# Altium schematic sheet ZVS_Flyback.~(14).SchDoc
size 431 x 279 mm; Date: Not shown in title block; ApprovedBy: Not shown in title block; CheckedBy: Not shown in title block; Author: Not shown in title block; CompanyName: Not shown in title block; Engineer: Not shown in title block; Organization: Not shown in title block; Address1: Not shown in title block; Address2: Not shown in title block; Address3: Not shown in title block; Address4: Not shown in title block; DocumentNumber: 2; Revision: Use project parameter SCH_Rev; SheetNumber: 2; SheetTotal: 2; PageSetup: Record=PageOptions¦CenterHorizontal=True¦CenterVertical=True¦PrintScale=1.00¦XCorrection=1.00¦YCorrection=1.00¦PrintKind=0¦BorderSize=5000000¦LeftOffset=0¦BottomOffset=0¦Orientation=2¦PaperLength=1000¦PaperWidth=1000¦Scale=100¦PaperSource=15¦PrintQuality=600¦MediaType=1¦DitherType=10¦PaperKind=Letter¦PrintScaleMode=1
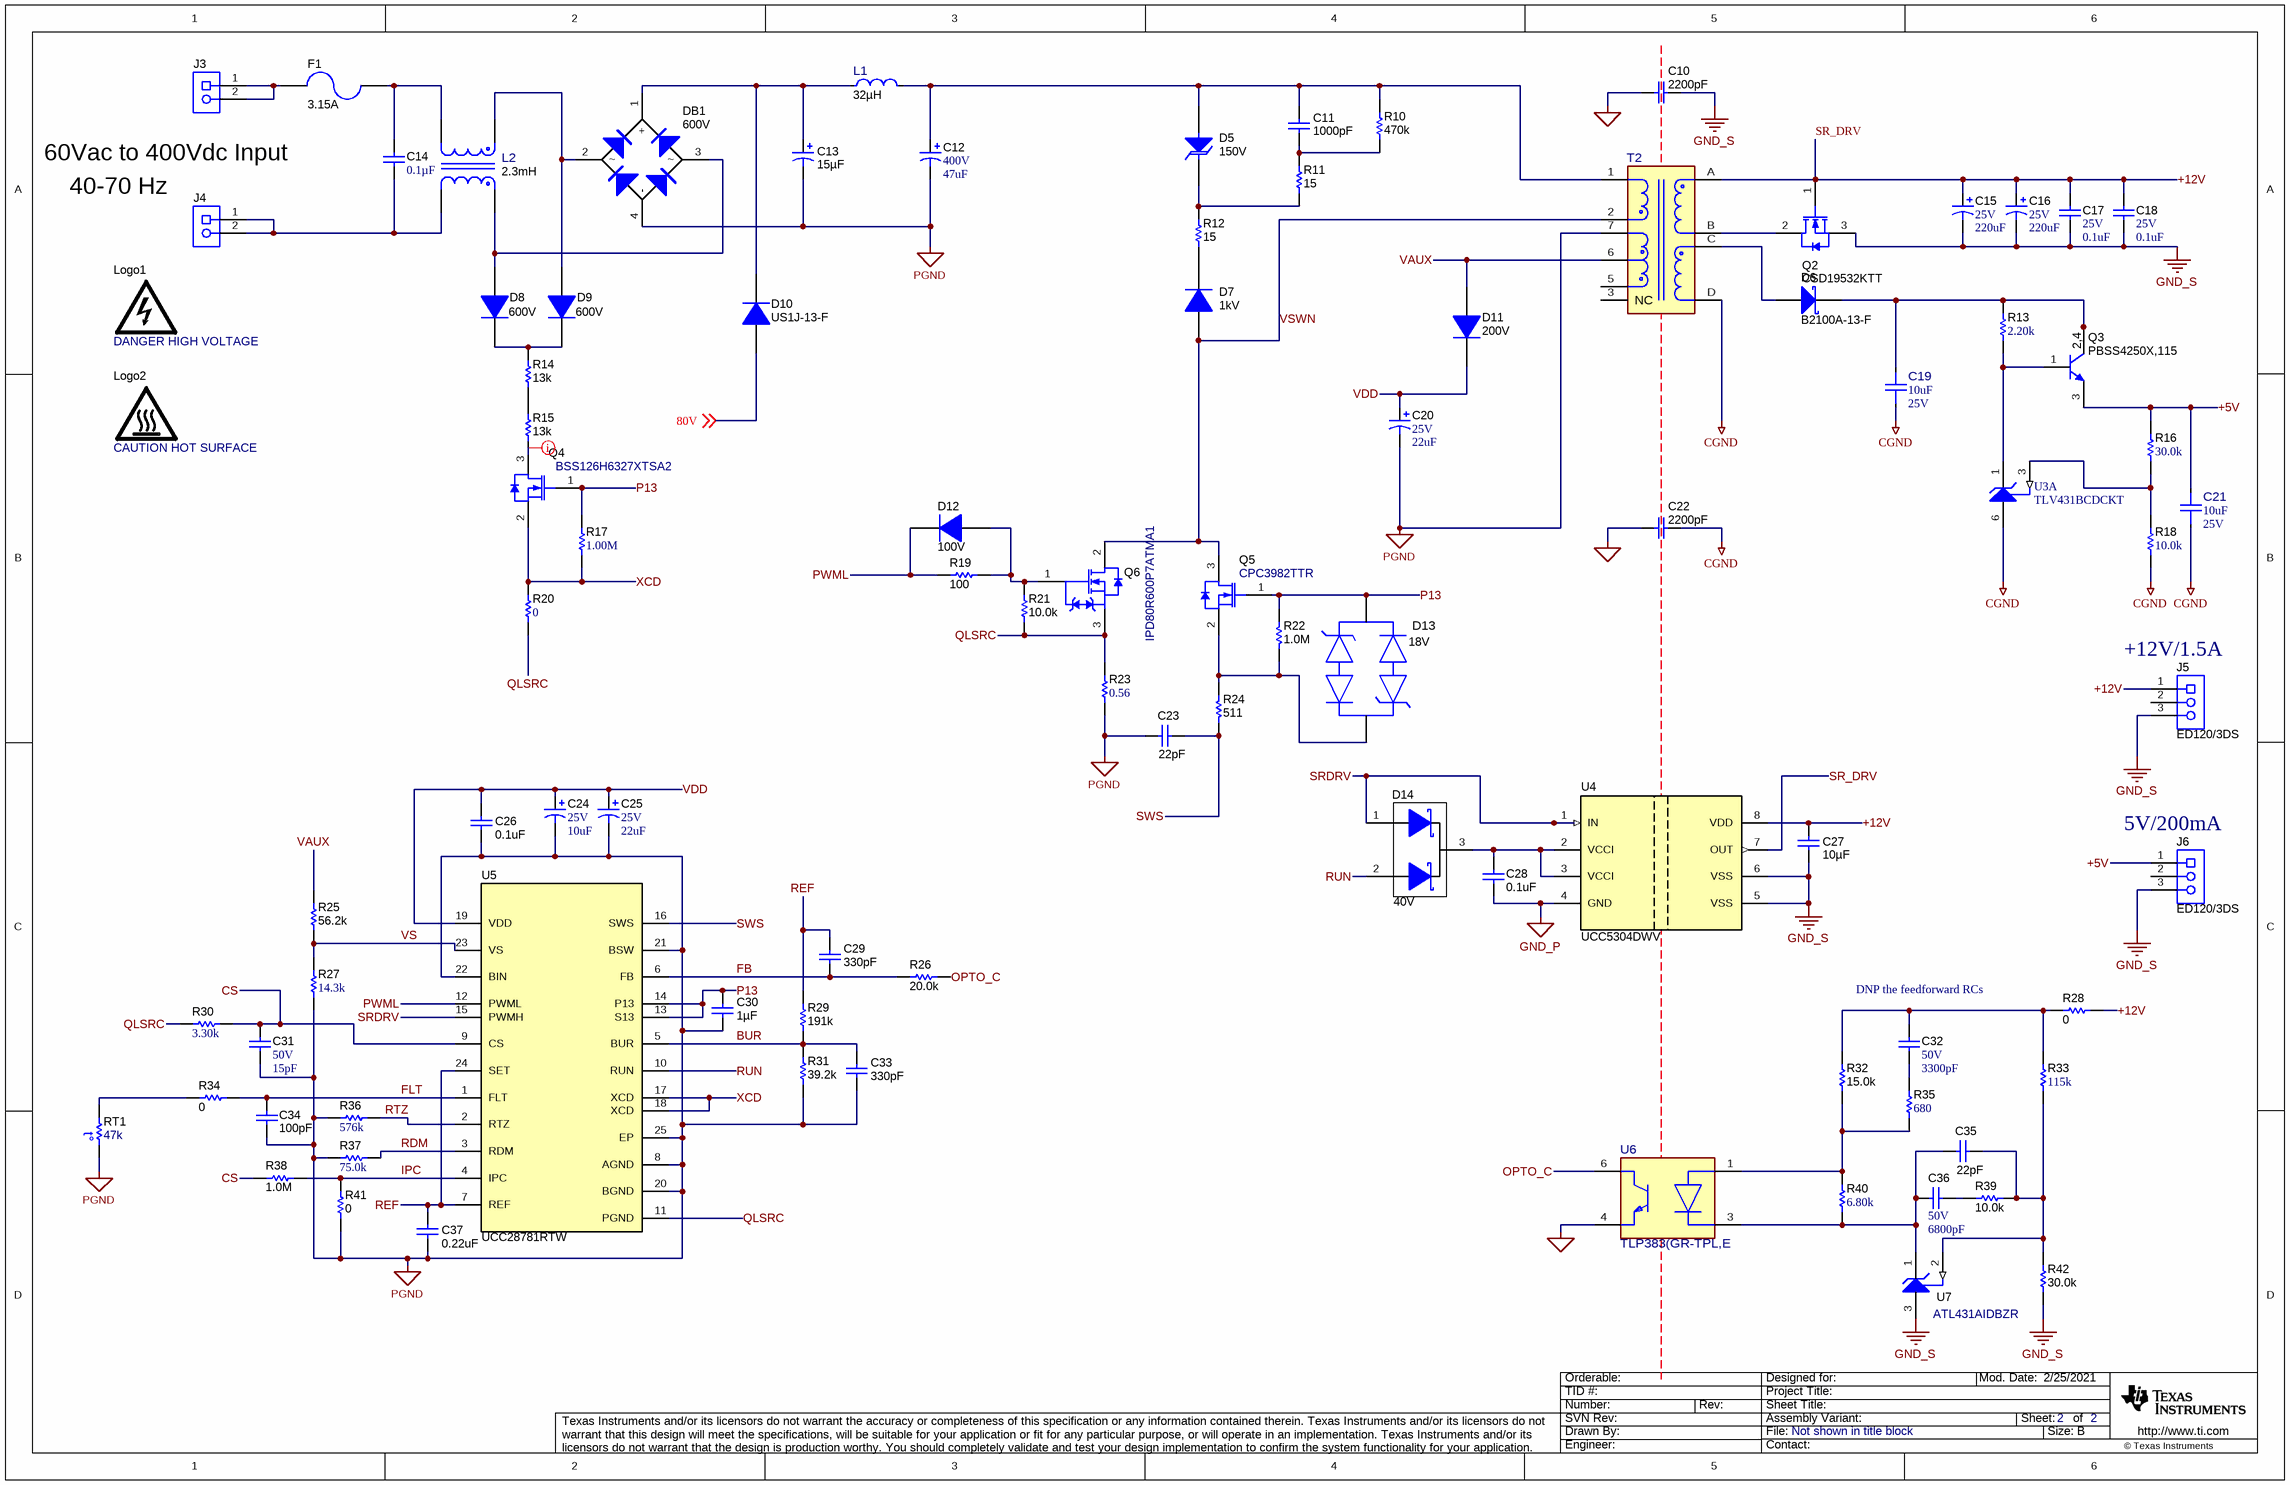
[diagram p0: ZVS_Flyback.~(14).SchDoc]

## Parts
C10  ValueDisplayed: 2200pF  [C900_9x13]  (hidden comment: C921U222MVVDBA7317)
C11  ValueDisplayed: 1000pF  [1206L]  (hidden comment: GRM31BR72J102KW01L)
C12  VDC_V: 400V  ValueDisplayed: 47uF  [CAPPR7.5-16x25]  (hidden comment: UCS2G470MHD)
C13  ValueDisplayed: 15µF  [UVC_1000x1600]  (hidden comment: UVC2G150MPD)
C14  ValueDisplayed: 0.1µF  [B32933_600x1500x2650]  (hidden comment: B32933A3104K000)
C15  VDC_V: 25V  ValueDisplayed: 220uF  [BT_1000x1250]  (hidden comment: UBT1E221MPD1TD)
C16  VDC_V: 25V  ValueDisplayed: 220uF  [BT_1000x1250]  (hidden comment: UBT1E221MPD1TD)
C17  VDC_V: 25V  ValueDisplayed: 0.1uF  [0603]  (hidden comment: 06033D104KAT2A)
C18  VDC_V: 25V  ValueDisplayed: 0.1uF  [0603]  (hidden comment: 06033D104KAT2A)
C19  ValueDisplayed: 10uF  VDC_V: 25V  [FP-ZRB18AR61E106ME01L_0603-MFG]  (hidden comment: ZRB18AR61E106ME01L)
C20  VDC_V: 25V  ValueDisplayed: 22uF  [SM_RADIAL_D]  (hidden comment: EEE-FC1E220P)
C21  ValueDisplayed: 10uF  VDC_V: 25V  [FP-ZRB18AR61E106ME01L_0603-MFG]  (hidden comment: ZRB18AR61E106ME01L)
C22  ValueDisplayed: 2200pF  [C900_9x13]  (hidden comment: C921U222MVVDBA7317)
C23  ValueDisplayed: 22pF  [0402S]  (hidden comment: GCM1555C1H220JA16D)
C24  VDC_V: 25V  ValueDisplayed: 10uF  [CAPSMT_62_D55]  (hidden comment: EMVA250ADA100MD55G)
C25  VDC_V: 25V  ValueDisplayed: 22uF  [SM_RADIAL_D]  (hidden comment: EEE-FC1E220P)
C26  ValueDisplayed: 0.1uF  [0402S]  (hidden comment: GRM155R71H104ME14D)
C27  ValueDisplayed: 10µF  [1206_180L]  (hidden comment: C1206C106J3RACAUTO)
C28  ValueDisplayed: 0.1uF  [0402S]  (hidden comment: GRM155R71H104ME14D)
C29  ValueDisplayed: 330pF  [0402S]  (hidden comment: GRM155R71H331KA01D)
C30  Cap_F: 1µF  [0603S]  (hidden comment: CGA3E1X7R1V105K080AC)
C31  VDC_V: 50V  ValueDisplayed: 15pF  [0402]  (hidden comment: CC0402JRNPO9BN150)
C32  VDC_V: 50V  ValueDisplayed: 3300pF  [0402]  (hidden comment: GRM155R71H332KA01D)
C33  ValueDisplayed: 330pF  [0402S]  (hidden comment: GRM155R71H331KA01D)
C34  ValueDisplayed: 100pF  [0402S]  (hidden comment: GRM1555C1H101JA01D)
C35  ValueDisplayed: 22pF  [0402S]  (hidden comment: GCM1555C1H220JA16D)
C36  VDC_V: 50V  ValueDisplayed: 6800pF  [0402]  (hidden comment: GRM155R71H682KA88D)
C37  ValueDisplayed: 0.22uF  [0402S]  (hidden comment: GRM155R71C224KA12D)
D5  VRWM: 150V  [SMA]  (hidden comment: SMAJ150A)
D6  B2100A-13-F  [SMA]
D7  Vr_V: 1kV  [SMA]  (hidden comment: MRA4007T3G)
D8  Vr_V: 600V  [TUMD2SM]  (hidden comment: RFU02VSM6STR)
D9  Vr_V: 600V  [TUMD2SM]  (hidden comment: RFU02VSM6STR)
D10  US1J-13-F  [SMA]
D11  Vr_V: 200V  [SOD-123H]  (hidden comment: CSFMT104-HF)
D12  Vr_V: 100V  [SOD-323]  (hidden comment: BAS316,115)
D13  CDSOD323-T18C  [FP-CDSOD323-T18C_SOD323-MFG]  (value not drawn)
D14  Vr_V: 40V  [SOT-323]  (hidden comment: BAS40W-05-7-F)
DB1  value 600V  [Z4-D]  (hidden comment: Z4DGP406L-HF)
F1  Irating_A: 3.15A  [FUSE_392]  (hidden comment: 39213150000)
J3  ED120/2DS  [On-Shore_ED120_2DS]  (value not drawn)
J4  ED120/2DS  [On-Shore_ED120_2DS]  (value not drawn)
J5  ED120/3DS  [On-Shore_ED120_3DS]
J6  ED120/3DS  [On-Shore_ED120_3DS]
L1  Ind_H: 32µH  [FP-7447052_PTH_D10MM0-MFG]  (hidden comment: 7447052)
L2  Ind_H: 2.3mH  [FP-RLTI-1387_PTH_CMC_0IN38_0IN60-MFG]  (hidden comment: RLTI-1387)
Logo1  DANGER HIGH VOLTAGE  [IEC_HighVoltage_Small]  (no BOM)
Logo2  CAUTION HOT SURFACE  [IEC_HotSurface_Small]  (no BOM)
Q2  CSD19532KTT  [KTT0002A]
Q3  PBSS4250X,115  [SOT-89-3]
Q4  BSS126H6327XTSA2  [SOT-23L]
Q5  CPC3982TTR  [SOT-23L]
Q6  IPD80R600P7ATMA1  [DPAK]
R10  ValueDisplayed: 470k  [0805_HV1]  (hidden comment: CRCW0805470KJNEA)
R11  ValueDisplayed: 15  [0805_HV1]  (hidden comment: CRCW080515R0JNEA)
R12  ValueDisplayed: 15  [0805_HV1]  (hidden comment: CRCW080515R0JNEA)
R13  ValueDisplayed: 2.20k  [0603]  (hidden comment: RC0603FR-072K2L)
R14  ValueDisplayed: 13k  [1206L]  (hidden comment: CRCW120613K0JNEA)
R15  ValueDisplayed: 13k  [1206L]  (hidden comment: CRCW120613K0JNEA)
R16  ValueDisplayed: 30.0k  [0603]  (hidden comment: RC0603FR-0730KL)
R17  ValueDisplayed: 1.00M  [0603]  (hidden comment: MCT06030C1004FP500)
R18  ValueDisplayed: 10.0k  [0402]  (hidden comment: ERJ-2RKF1002X)
R19  ValueDisplayed: 100  [0805_HV1]  (hidden comment: CRCW0805100RJNEA)
R20  ValueDisplayed: 0  [0603]  (hidden comment: RC0603JR-070RL)
R21  ValueDisplayed: 10.0k  [0402S]  (hidden comment: CRCW040210K0FKED)
R22  ValueDisplayed: 1.0M  [0402S]  (hidden comment: CRCW04021M00JNED)
R23  ValueDisplayed: 0.56  [1206]  (hidden comment: ERJ-8RQFR56V)
R24  ValueDisplayed: 511  [0402S]  (hidden comment: CRCW0402511RFKED)
R25  ValueDisplayed: 56.2k  [0402S]  (hidden comment: CRCW040256K2FKED)
R26  ValueDisplayed: 20.0k  [0402S]  (hidden comment: CRCW040220K0FKED)
R27  ValueDisplayed: 14.3k  [0402]  (hidden comment: CRCW040214K3FKED)
R28  ValueDisplayed: 0  [0402S]  (hidden comment: RC0402JR-070RL)
R29  ValueDisplayed: 191k  [0402S]  (hidden comment: CRCW0402191KFKED)
R30  ValueDisplayed: 3.30k  [0402]  (hidden comment: RK73H1ETTP3301F)
R31  ValueDisplayed: 39.2k  [0402S]  (hidden comment: CRCW040239K2FKED)
R32  ValueDisplayed: 15.0k  [0402S]  (hidden comment: CRCW040215K0FKED)
R33  ValueDisplayed: 115k  [0402]  (hidden comment: RC1005F1153CS)
R34  ValueDisplayed: 0  [0402S]  (hidden comment: CRCW04020000Z0EDHP)
R35  ValueDisplayed: 680  [0603]  (hidden comment: RC0603FR-07680RL)
R36  ValueDisplayed: 576k  [0402]  (hidden comment: CRCW0402576KFKED)
R37  ValueDisplayed: 75.0k  [0402]  (hidden comment: CRCW040275K0FKED)
R38  ValueDisplayed: 1.0M  [0402S]  (hidden comment: CRCW04021M00JNED)
R39  ValueDisplayed: 10.0k  [0402S]  (hidden comment: CRCW040210K0FKED)
R40  ValueDisplayed: 6.80k  [0603]  (hidden comment: RC0603FR-076K8L)
R41  ValueDisplayed: 0  [0402S]  (hidden comment: CRCW04020000Z0EDHP)
R42  ValueDisplayed: 30.0k  [0402S]  (hidden comment: CRCW040230K0FKED)
RT1  value 47k  [0603S]  (hidden comment: NCP18WB473J03RB)
T2  RLTI-1324  [FP-RLTI-1324_PTH_0IN980_0IN766-MFG]  (value not drawn)
U3  TLV431BCDCKT  [DCK0006A_N]  (part A of 2)
U4  UCC5304DWV  [DWV0008A]
U5  UCC28781RTW  [RTW0024B]
U6  TLP383(GR-TPL,E  [FP-TLP383(GR-TPL,E_SO6-4-MFG]
U7  ATL431AIDBZR  [DBZ0003A_L]

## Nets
CGND: C19.1 C21.1 C22.1 R18.1 T2.D U3.6(ANODE)
GND2: C10.2 C22.2 U6.4(Emitter)
GND_P: C28.2 U4.4(GND)
GND_S: C10.1 C15.2(-) C16.2(-) C17.2 C18.2 C27.2 J5.3 J6.3 Q2.3(S) R42.2 U4.5(VSS) U4.6(VSS) U7.3(ANODE)
PGND: C12.2(-) C13.2(-) C20.2(-) C23.1 C24.2(-) C25.2(-) C26.2 C30.2 C31.2 C33.2 C34.1 C37.2 DB1.4(-) R23.1 R27.1 R31.2 R36.1 R37.1 R41.1 RT1.2 T2.7 U5.8(AGND) U5.20(BGND) U5.21(BSW) U5.22(BIN) U5.25(EP)
80V: D10.2(A) ; off-sheet 80V
+5V: C21.2 J6.1 Q3.3(E) R16.2
+12V: C15.1(+) C16.1(+) C17.1 C18.1 C27.1 J5.1 Q2.1(G) R28.1 T2.A U4.7(OUT) U4.8(VDD)  [also labelled SR_DRV]
BUR: C33.1 R29.2 R31.1 U5.5(BUR)
CS: C31.1 R30.2 R38.2 U5.9(CS)
FB: C29.2 R26.1 U5.6(FB)
FLT: C34.2 R34.2 U5.1(FLT)
IPC: R38.1 R41.2 U5.4(IPC)
OPTO_C: R26.2 U6.6(Collector)
P13: C30.1 D13.2 Q4.1(G) Q5.1(G) R17.2 R22.2 U5.13(S13) U5.14(P13)
PWML: D12.1(K) R19.1 U5.12(PWML)
QLSRC: Q6.3(S) R20.1 R21.1 R23.2 R30.1 U5.11(PGND)
RDM: R37.2 U5.3(RDM)
REF: C29.1 C37.1 R29.1 U5.7(REF) U5.24(SET)
RTZ: R36.2 U5.2(RTZ)
RUN: D14.2(A) U5.10(RUN)
SRDRV: D14.1(A) U4.1(IN) U5.15(PWMH)
SWS: C23.2 R24.1 U5.16(SWS)
VAUX: D11.2(A) R25.1 T2.6
VDD: C20.1(+) C24.1(+) C25.1(+) C26.1 D11.1(K) U5.19(VDD)
VS: R25.2 R27.2 U5.23(VS)
VSWN: D7.2(A) Q5.3(D) Q6.2(D) T2.2
XCD: Q4.2(S) R17.1 R20.2 U5.17(XCD) U5.18(XCD)
NetC11_1: C11.1 C12.1(+) D5.2(A) L1.2 R10.2 T2.1
NetC11_2: C11.2 R10.1 R11.2
NetC13_1: C13.1(+) D10.1(K) DB1.1(+) L1.1
NetC14_1: C14.1 F1.1 L2.3
NetC14_2: C14.2 J4.1 J4.2 L2.2
NetC19_2: C19.2 D6.1(K) Q3.2(C) Q3.4(C) R13.2
NetC28_1: C28.1 D14.3(K) U4.2(VCCI) U4.3(VCCI)
NetC32_1: C32.1 R28.2 R32.2 R33.2
NetC32_2: C32.2 R35.2
NetC35_1: C35.1 C36.2 R40.1 U6.3(Cathode) U7.1(CATHODE)
NetC35_2: C35.2 R33.1 R39.2 R42.1 U7.2(REF)
NetC36_1: C36.1 R39.1
NetD5_1: D5.1(K) R11.1 R12.2
NetD6_2: D6.2(A) T2.C
NetD7_1: D7.1(K) R12.1
NetD8_1: D8.1(K) D9.1(K) R14.1
NetD8_2: D8.2(A) DB1.3 L2.1
NetD9_2: D9.2(A) DB1.2 L2.4
NetD12_2: D12.2(A) Q6.1(G) R19.2 R21.2
NetD13_1: D13.1 Q5.2(S) R22.1 R24.2
NetF1_2: F1.2 J3.1 J3.2
NetQ2_2: Q2.2(D) T2.B
NetQ3_1: Q3.1(B) R13.1 U3.1(CATHODE)
NetQ4_3: Q4.3(D) R15.2
NetR14_2: R14.2 R15.1
NetR16_1: R16.1 R18.2 U3.3(REF)
NetR32_1: R32.1 R35.1 R40.2 U6.1(Anode)
NetR34_1: R34.1 RT1.1

Not connected (* = marked no-connect by the designer): J5 2; J6 2; T2 3(NC) 5

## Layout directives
net class HV: NetQ4_3

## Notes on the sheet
- 60Vac to 400Vdc Input
- 40-70 Hz
- (near D13) 18V
- (near J5) +12V/1.5A
- (near J6) 5V/200mA
- (near C32) DNP the feedforward RCs

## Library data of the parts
C10 C22 = CMP-0078358-1: CAP, CERM, 2200 pF, X1 400 VAC/Y1 400 VAC, +/- 20%, Y5V, D9xL13mm; Manufacturer: Kemet; Cap_F: 2.2nF; SizeAreaWB_mm2: 121; VAC_X: 400V; SizeArea_mm2: 81; AEC Qualified: N; AEC Category: Q200; Value: 2200pF; TaMax_C: 125°C; SizeZ_mm: 13; TaMin_C: -40°C; SizeY_mm: 9; U/M: EA; AC_Safety: X1Y1; Cap_Case: 9x13mm
C11 = CMP-0008909-2: CAP, CERM, 1000 pF, 630 V, +/- 10%, X7R, 1206; Manufacturer: MuRata; TaMin_C: -55°C; Polarized: N; SizeAreaWB_mm2: 10.92; Value1: Unknown; U/M: EA; Value: 1000pF; TaMax_C: 125°C; SizeZ_mm: 1.35; SizeX_mm: 3.2; SizeY_mm: 1.6; Cap_Case: 1206; Value2: 630V; SizeArea_mm2: 5.12; Cap_F: 1nF; AEC Category: Q200
C12 = CMP-0010241-2: CAP, AL, 47 uF, 400 V, +/- 20%, TH; Manufacturer: Nichicon; TaMin_C: -40°C; Polarized: Y; SizeAreaWB_mm2: 324; Value1: Unknown; U/M: EA; Value: 47uF; TaMax_C: 105°C; SizeZ_mm: 25; SizeX_mm: 16; Cap_Case: Radial  16x25mm; SizeArea_mm2: 256; CompType: Capacitor; AEC Qualified: N; Cap_F: 47µF; IRMS_A: 1.18A; AEC Category: Q200
C13 = CMP-0860955-2: CAP, AL, 15 µF, 400 V, +/- 20%, AEC-Q200 Grade 2, TH; Manufacturer: Nichicon; SizeArea_mm2: 100; CompType: Capacitor; Value2: 400V; SizeZ_mm: 18; IRMS_A: 180mA; Polarized: Y; SizeX_mm: 10; Value: 15uF; TaMin_C: -40°C; AEC Grade: 2; U/M: EA; SizeAreaWB_mm2: 144; Cap_Case: 10x16; TaMax_C: 105°C; AEC Category: Q200
C14 = CMP-0077664-2: CAP, Film, 0.1 µF, X2 305 VAC, +/- 10%, AEC-Q200 Grade 2, TH; Manufacturer: TDK; TaMin_C: -40°C; Polarized: N; SizeAreaWB_mm2: 210.0; Value: 0.1uF; TaMax_C: 105°C; VAC_X: 305; SizeZ_mm: 15.0; SizeX_mm: 26.0; SizeY_mm: 5.5; SizeArea_mm2: 143.0; AEC Qualified: Y; Cap_F: 100nF; AEC Grade: 2; AEC Category: Q200
C15 C16 = CMP-0010527-1: CAP, AL, 220 uF, 25 V, +/- 20%, 0.1 ohm, TH; Manufacturer: Nichicon; TaMin_C: -40°C; ESR_ohm: 1d; Polarized: Y; SizeAreaWB_mm2: 144; Value1: 0.1 ohm; U/M: EA; Value: 220uF; TaMax_C: 125°C; SizeZ_mm: 14.5; SizeX_mm: 10; Cap_Case: 10x12.5mm; SizeArea_mm2: 100; CompType: Capacitor; Cap_F: 220µF; IRMS_A: 6.8dA; AEC Category: Q200
C17 C18 = CMP-0006758-5: CAP, CERM, 0.1 uF, 25 V, +/- 10%, X5R, 0603; Manufacturer: AVX; TaMin_C: -55°C; ESR_ohm: 0.048; Polarized: N; SizeAreaWB_mm2: 4.68; Value1: 0.048 ohm; U/M: EA; Value: 0.1uF; TaMax_C: 85°C; SizeZ_mm: 1; SizeX_mm: 1.6; SizeY_mm: 0.8; SizeArea_mm2: 1.28; Cap_F: 100nF; IRMS_A: 5.3dA; AEC Category: Q200
C19 C21 = CMP-0094458-1: 10µF ±20% 25V Ceramic Capacitor X5R 0603 (1608 Metric); Manufacturer: Murata Electronics; SizeZ_mm: 1.2mm; AEC Qualified: No
C20 C25 = CMP-0010654-1: CAP, AL, 22 uF, 25 V, +/- 20%, 1 ohm, SMD; Manufacturer: Panasonic; TaMin_C: -40°C; ESR_ohm: 1; Polarized: Y; SizeAreaWB_mm2: 84.28; Value1: 1 ohm; U/M: EA; Value: 22uF; TaMax_C: 105°C; SizeZ_mm: 5.4; SizeX_mm: 7.8; SizeY_mm: 6.6; Cap_Case: D; SizeArea_mm2: 51.48; CompType: Capacitor; Cap_F: 22µF; IRMS_A: 1.15dA; AEC Category: Q200
C23 C35 = CMP-0006348-2: CAP, CERM, 22 pF, 50 V, +/- 5%, C0G/NP0, AEC-Q200 Grade 1, 0402; Manufacturer: MuRata; TaMin_C: -55°C; Polarized: N; SizeAreaWB_mm2: 3; Value1: Unknown; U/M: EA; Value: 22pF; TaMax_C: 125°C; SizeZ_mm: 0.6; SizeX_mm: 1; SizeY_mm: 0.5; Cap_Case: 0402; Value2: 50V; AEC Qualified: Y; AEC Category: Q200
C24 = CMP-0010785-1: CAP, AL, 10 uF, 25 V, +/- 20%, SMD; Manufacturer: Chemi-Con; TaMin_C: -40°C; Polarized: Y; SizeAreaWB_mm2: 28.09; Value1: Unknown; U/M: EA; Value: 10uF; TaMax_C: 85°C; SizeZ_mm: 5.2; SizeX_mm: 4.3; Cap_Case: D55; SizeArea_mm2: 18.49; CompType: Capacitor; Cap_F: 10µF; IRMS_A: 24mA; AEC Category: Q200
C26 C28 = CMP-0006675-2: CAP, CERM, 0.1 uF, 50 V, +/- 20%, X7R, 0402; Manufacturer: MuRata; TaMin_C: -55°C; Polarized: N; SizeAreaWB_mm2: 3; Value1: Unknown; U/M: EA; Value: 0.1uF; TaMax_C: 125°C; SizeZ_mm: 0.6; SizeX_mm: 1; SizeY_mm: 0.5; Cap_Case: 0402; Value2: 50V; Cap_F: 100nF; AEC Category: Q200
C27 = CMP-0081062-1: CAP, CERM, 10 µF, 25 V,+/- 5%, X7R, AEC-Q200 Grade 1, 1206; Manufacturer: Kemet; TaMin_C: -55°C; Polarized: N; SizeAreaWB_mm2: 10.92; U/M: EA; Value: 10uF; TaMax_C: 125°C; SizeZ_mm: 1.8; SizeX_mm: 3.2; SizeY_mm: 1.6; Cap_Case: 1206_180; Value2: 25V; SizeArea_mm2: 5.12; AEC Qualified: Y; AEC Grade: 1; AEC Category: Q200
C29 C33 = CMP-0006687-2: CAP, CERM, 330 pF, 50 V, +/- 10%, X7R, 0402; Manufacturer: MuRata; TaMin_C: -55°C; Polarized: N; SizeAreaWB_mm2: 3; Value1: Unknown; U/M: EA; Value: 330pF; TaMax_C: 125°C; SizeZ_mm: 0.6; SizeX_mm: 1; SizeY_mm: 0.5; Cap_Case: 0402; Value2: 50V; AEC Category: Q200
C30 = CMP-0007067-4: CAP, CERM, 1 uF, 35 V, +/- 10%, X7R, AEC-Q200 Grade 1, 0603; Manufacturer: TDK; TaMin_C: -55°C; ESR_ohm: 5.522m; Polarized: N; SizeAreaWB_mm2: 4.68; Value1: 0.005522 ohm; U/M: EA; Value: 1uF; TaMax_C: 125°C; SizeZ_mm: 1; SizeX_mm: 1.6; SizeY_mm: 0.8; Cap_Case: 0603; Value2: 35V; SizeArea_mm2: 1.28; AEC Qualified: Y; IRMS_A: 2.21617A; AEC Category: Q200
C31 = CMP-0006304-2: CAP, CERM, 15 pF, 50 V, +/- 5%, C0G/NP0, 0402; Manufacturer: Yageo America; TaMin_C: -55°C; Polarized: N; SizeAreaWB_mm2: 3; Value1: Unknown; U/M: EA; Value: 15pF; TaMax_C: 125°C; SizeZ_mm: 0.6; SizeX_mm: 1; SizeY_mm: 0.5; AEC Category: Q200
C32 = CMP-0006688-2: CAP, CERM, 3300 pF, 50 V, +/- 10%, X7R, 0402; Manufacturer: MuRata; TaMin_C: -55°C; Polarized: N; SizeAreaWB_mm2: 3; Value1: Unknown; U/M: EA; Value: 3300pF; TaMax_C: 125°C; SizeZ_mm: 0.6; SizeX_mm: 1; SizeY_mm: 0.5; Cap_F: 3.3nF; AEC Category: Q200
C34 = CMP-0006410-2: CAP, CERM, 100 pF, 50 V, +/- 5%, C0G/NP0, 0402; Manufacturer: MuRata; TaMin_C: -55°C; Polarized: N; SizeAreaWB_mm2: 3; Value1: Unknown; U/M: EA; Value: 100pF; TaMax_C: 125°C; SizeZ_mm: 0.6; SizeX_mm: 1; SizeY_mm: 0.5; Cap_Case: 0402; Value2: 50V; AEC Category: Q200
C36 = CMP-0006696-2: CAP, CERM, 6800 pF, 50 V, +/- 10%, X7R, 0402; Manufacturer: MuRata; TaMin_C: -55°C; Polarized: N; SizeAreaWB_mm2: 3; Value1: Unknown; U/M: EA; Value: 6800pF; TaMax_C: 125°C; SizeZ_mm: 0.6; SizeX_mm: 1; SizeY_mm: 0.5; Cap_F: 6.8nF; AEC Category: Q200
C37 = CMP-0006648-2: CAP, CERM, 0.22 uF, 16 V, +/- 10%, X7R, 0402; Manufacturer: MuRata; TaMin_C: -55°C; Polarized: N; SizeAreaWB_mm2: 3; Value1: Unknown; U/M: EA; Value: 0.22uF; TaMax_C: 125°C; SizeZ_mm: 0.6; SizeX_mm: 1; SizeY_mm: 0.5; Cap_Case: 0402; Value2: 16V; Cap_F: 220nF; AEC Category: Q200
D5 = CMP-0084982-1: Diode, TVS, Uni, 150 V, 243 Vc, 400 W, 1.6 A, SMA; Manufacturer: Littelfuse; Vc: 243V; Ipp: 1.6A; RJA_CperW: 120; AEC Qualified: N; Value: 150V; Ppk: 400W; AEC Category: Q101; SizeArea_mm2: 16.3228; SizeAreaWB_mm2: 37.3428; SizeZ_mm: 2.87; Vbr_Max: 185V; SizeX_mm: 5.59; SizeY_mm: 2.92; Vbr_Min: 167V
D6 = CMP-0081099-2: Diode, Schottky, 100 V, 2 A, SMA; Manufacturer: Diodes Inc.; SizeZ_mm: 2.87; SizeX_mm: 5.59; AEC Qualified: N; Value2: 0.79V; SizeArea_mm2: 16.3228; Vf_V: 790mV; AEC Category: Q101; TJmax_C: 125°C; Vr_V: 100V; Value: 100V; Io_A: 2A; SizeAreaWB_mm2: 37.3428; SizeY_mm: 2.92
D7 = CMP-0077082-2: Diode, Standard Recovery Rectifier, 1000 V, 1 A, AEC-Q101, SMA; Manufacturer: ON Semiconductor; SizeAreaWB_mm2: 37.3428; SizeArea_mm2: 16.3228; AEC Qualified: Y; TJmax_C: 175°C; AEC Category: Q101; Value: 1000V; SizeZ_mm: 2.87; Green_REACh: Passed; Io_A: 1A; Vf_V: 1.1V; SizeY_mm: 2.92; Green_Lifecycle: Active; SizeX_mm: 5.59; RJC_CperW: 16.2
D8 D9 = CMP-0080762-2: Diode, Standard Recovery Rectifier, 600 V, 0.2 A, 2x1.4mm; Manufacturer: Rohm; SizeArea_mm2: 3.5; AEC Qualified: N; SizeY_mm: 1.4; Io_A: 200mA; SizeZ_mm: 0.8; Vf_V: 2.2V; SizeAreaWB_mm2: 8.4; TJmax_C: 150°C; Value1: 0.2A; SizeX_mm: 2.5; AEC Category: Q101; Value: 600V
D10 = CMP-0077027-2: Diode, Ultrafast, 600 V, 1 A, SMA; Manufacturer: Diodes Inc.; Value: 600V; TJmax_C: 150°C; Value1: 1A; Value2: 1.7V; SizeY_mm: 2.92; Green_REACh: Passed; Green_Lifecycle: Active; SizeX_mm: 5.59; AEC Category: Q101; SizeAreaWB_mm2: 37.3428; SizeZ_mm: 2.87; SizeArea_mm2: 16.3228
D11 = CMP-0029199-2: Diode, Superfast Rectifier, 200 V, 1 A, 3.5x1.6mm; Manufacturer: Comchip Technology; Vf_V: 950mV; Value: 200V; Value1: 1A; Value2: 0.95V; TJmax_C: 150°C; SizeAreaWB_mm2: 11.7; SizeArea_mm2: 5.6; SizeX_mm: 3.5; SizeY_mm: 1.6; SizeZ_mm: 1; AEC Category: Q101; AEC Qualified: N
D12 = CMP-0029006-2: Diode, Ultrafast, 100 V, 0.25 A, SOD-323; Manufacturer: Nexperia; SizeY_mm: 1.35; Value1: 0.25A; SizeAreaWB_mm2: 8.695; SizeZ_mm: 1; Io_A: 250mA; Value2: 1.4V; SizeX_mm: 2.7; Green_REACh: Incomplete; TJmax_C: 150°C; Green_Lifecycle: Not Set; AEC Category: Q101; Value: 100V; SizeArea_mm2: 3.645
D13 = CMP-0087587-1: Diode, TVS, Bi, 18 V, SOD-323; Manufacturer: Bourns Inc.; SizeZ_mm: 1.14mm; AEC Qualified: No
D14 = CMP-0028437-2: Diode, Schottky, 40 V, 0.2 A, SOT-323; Manufacturer: Diodes Inc.; Io_A: 200mA; Green_Lifecycle: Not Set; SizeAreaWB_mm2: 10.24; Green_REACh: Incomplete; Value1: 0.2A; Value: 40V; SizeZ_mm: 1.1; SizeX_mm: 2.2; Vf_V: 800mV; Value2: 0.8V; SizeArea_mm2: 4.84; AEC Category: Q101
DB1 = Z4DGP406L-HF: Diode, P-N-Bridge, 600 V, 4 A, Z4-D; Manufacturer: Comchip Technology; U/M: EA; Vf_V: 0.95; Value1: 4A; Value2: 0.95V; Io_A: 4; Vr_V: 600; TJmax_C: 175; SizeAreaWB_mm2: 126.25; SizeArea_mm2: 85.05; SizeX_mm: 10.5; SizeY_mm: 8.1; SizeZ_mm: 1.55; AEC Category: Q101; AEC Qualified: N; Green_Lifecycle: Not Set; Green_REACh: Incomplete
F1 = CMP-0003561-2: Fuse, 3.15 A, 250VAC/VDC, TH; Manufacturer: Littelfuse; VAC_V: 250V
J3 J4 = CMP-0074910-1: Terminal Block, 5.08 mm, 2x1, Brass, TH; Manufacturer: On-Shore Technology; Pitch_mm: 5.08; Gender: Female; Shrouded: N; Row_Count: 1; Current_A: 15A; Voltage_V: 300V; Cert_CULUS: Y; CNHeader: False; CT: True; Green_Lifecycle: Not Set; Green_REACh: Incomplete
J5 J6 = CMP-0074911-1: Terminal Block, 5.08 mm, 3x1, Brass, TH; Manufacturer: On-Shore Technology; Cert_VDE: Y; CNHeader: False; Current_A: 15A; Green_Lifecycle: Not Set; Shrouded: N; Gender: Female; Green_REACh: Incomplete; Voltage_V: 300V; Row_Count: 1; Pitch_mm: 5.08; CT: True
L1 = CMP-0087546-1: WE-FI Leaded Toroidal Line Choke; Manufacturer: Wurth; SizeZ_mm: 10mm; Irms: 2.6A; DCR_ohm: 0.045; AEC Qualified: No; Symbol Name: SYM-7447052
L2 = CMP-0092946-1: Common Mode Choke, 2.3mH 35%, 0.6x0.38x0.75 IN; Manufacturer: Renco; Test Frequency: 10kHz; SizeZ_mm: 0.75inch; DCR_ohm: 0.03; AEC Qualified: No
Logo1 = CMP-0074835-1: IEC 61010-1 High Voltage Warning; SymbolCreator: a0412235
Logo2 = CMP-0074837-1: IEC 61010-1 Hot Surface Warning; SymbolCreator: a0412235
Q2 = CMP-0000957-3: MOSFET, N-CH, 100 V, 136 A, KTT0002A (TO-263-2); Alternate Manufacturer: None; Manufacturer: Texas Instruments; SizeZ_mm: 4.7; ChType: N; Value2: 44 nC; VdsMax_V: 100V; SizeX_mm: 14.3; SizeAreaWB_mm2: 198.208; SizeY_mm: 10.16; Vgs_V: 20V; QgTyp_nC: 44; Value: 100V; SizeArea_mm2: 145.288; AEC Category: Q101; IdsMax_A: 136A
Q3 = CMP-0000491-2: Transistor, NPN, 50 V, 2 A, SOT-89; Manufacturer: NXP Semiconductor; TaMax_C: 150°C; Value1: 2 A; Vcesat1_V: 2.5dV; SizeX_mm: 4.1; SizeY_mm: 4.5; TaMin_C: -65°C; IcRated_A: 2A; CompType: BJT; SizeZ_mm: 1.5; AEC Qualified: N; Value: 50 V; SizeArea_mm2: 18.45; NPN: 1; Vceo_V: 50V; PNP: 0; AEC Category: Q101; SizeAreaWB_mm2: 28.05; U/M: EA
Q4 = CMP-0067574-2: MOSFET, N-CH, Depletion Mode, 100 V, 0.17 A, AEC-Q101, SOT-23; Manufacturer: Infineon Technologies; Alternate Manufacturer: None; ChType: N; Value: 600V; Value1: ? ohm; Value2: 1.4 nC; QgTyp_nC: 1.4; Vgs_V: 20V; IdsMax_A: 21mA; SizeAreaWB_mm2: 14.0; SizeArea_mm2: 7.5; SizeX_mm: 2.5; SizeY_mm: 3.0; SizeZ_mm: 1.1; AEC Category: Q101; AEC Qualified: Y
Q5 = CMP-0081263-2: MOSFET, N-CH, Depletion Mode, 800 V, SOT-23; Alternate Manufacturer: None; Manufacturer: IXYS; SizeAreaWB_mm2: 14; Vgs_V: 15V; Value1: ? ohm; VdsMax_V: 800V; Value: 800V; SizeZ_mm: 1.1; SizeX_mm: 2.5; SizeY_mm: 3; Value2: ? nC; SizeArea_mm2: 7.5; ChType: N; AEC Category: Q101
Q6 = CMP-0083711-2: MOSFET, N-CH, 800 V, 8 A, DPAK; Manufacturer: Infineon Technologies; Alternate Manufacturer: None; AEC Qualified: N; Vgs_V: 20V; SizeY_mm: 6.54; VdsMax_V: 800V; IdsMax_A: 8A; SizeX_mm: 9.91; Value2: 20 nC; AEC Category: Q101; ChMode: Enhancement; SizeAreaWB_mm2: 101.7114; Value1: ? ohm; SizeArea_mm2: 64.8114; Value: 800V; SizeZ_mm: 2.29; QgTyp_nC: 20
R10 = CMP-0020554-3: RES, 470 k, 5%, 0.125 W, AEC-Q200 Grade 0, 0805; Manufacturer: Vishay-Dale; Power_W: 125mW; TempCo: 200 ppm/C; Value: 470k; EIA_Code: E24; SizeX_mm: 2; SizeY_mm: 1.25; SizeZ_mm: 1.45; Value2: 0.125W; SizeArea_mm2: 2.5; AEC Qualified: Y; VDC_V: 150V; AEC Category: Q200; AEC Grade: 0
R11 R12 = CMP-0020464-3: RES, 15, 5%, 0.125 W, AEC-Q200 Grade 0, 0805; Manufacturer: Vishay-Dale; Power_W: 125mW; TempCo: 200 ppm/C; Value_Code: 15R0; Value: 15; EIA_Code: E24; SizeX_mm: 2; SizeY_mm: 1.25; SizeZ_mm: 1.45; Value2: 0.125W; SizeArea_mm2: 2.5; AEC Qualified: Y; VDC_V: 150V; AEC Category: Q200; AEC Grade: 0
R13 = CMP-0022986-5: RES, 2.20 k, 1%, 0.1 W, 0603; Manufacturer: Yageo; Power_W: 100mW; TempCo: 100 ppm/C; Value_Code: 2k20; Value: 2.20k; Res_ohm: 2.2k; SizeX_mm: 1.6; SizeY_mm: 0.8; SizeZ_mm: 1; Value2: 0.1W; SizeArea_mm2: 1.28; AEC Qualified: N; VDC_V: 75V; AEC Category: Q200; SizeAreaWB_mm2: 4.68
R14 R15 = CMP-0018589-3: RES, 13 k, 5%, 0.25 W, AEC-Q200 Grade 0, 1206; Manufacturer: Vishay-Dale; Power_W: 250mW; TempCo: 200 ppm/C; Value_Code: 13k0; Value: 13k; EIA_Code: E24; SizeX_mm: 3.2; SizeY_mm: 1.6; SizeZ_mm: 1.35; Value2: 0.25W; SizeArea_mm2: 5.12; AEC Qualified: Y; VDC_V: 200V; AEC Category: Q200; AEC Grade: 0
R16 = CMP-0023020-5: RES, 30.0 k, 1%, 0.1 W, 0603; Manufacturer: Yageo; Power_W: 100mW; TempCo: 100 ppm/C; Value_Code: 30k0; Value: 30.0k; Res_ohm: 30k; SizeX_mm: 1.6; SizeY_mm: 0.8; SizeZ_mm: 1; Value2: 0.1W; SizeArea_mm2: 1.28; AEC Qualified: N; VDC_V: 75V; AEC Category: Q200; SizeAreaWB_mm2: 4.68
R17 = CMP-0022731-2: RES, 1.00 M, 1%, 0.125 W, 0603; Manufacturer: Vishay/Beyschlag; Power_W: 125mW; TempCo: 50 ppm/C; Value_Code: 1M00; U/M: EA; Value: 1.00Meg; EIA_Code: E96; Res_ohm: 1M; SizeX_mm: 1.6; SizeY_mm: 0.8; SizeZ_mm: 1; Value2: 0.125W; SizeArea_mm2: 1.28; AEC Qualified: N; VDC_V: 75V; AEC Category: Q200
R18 = CMP-0026658-1: RES, 10.0 k, 1%, 0.1 W, 0402; Manufacturer: Panasonic; Power_W: 100mW; TempCo: 100 ppm/C; Value_Code: 10k0; U/M: EA; Value: 10.0k; EIA_Code: E96; Res_ohm: 10k; SizeX_mm: 1; SizeY_mm: 0.5; SizeZ_mm: 0.6; Value2: 0.1W; VDC_V: 50V; AEC Category: Q200
R19 = CMP-0020445-3: RES, 100, 5%, 0.125 W, AEC-Q200 Grade 0, 0805; Manufacturer: Vishay-Dale; Power_W: 125mW; TempCo: 200 ppm/C; Value_Code: 100R; Value: 100; EIA_Code: E24; SizeX_mm: 2; SizeY_mm: 1.25; SizeZ_mm: 1.45; Value2: 0.125W; SizeArea_mm2: 2.5; AEC Qualified: Y; VDC_V: 150V; AEC Category: Q200; AEC Grade: 0
R20 = CMP-0025885-5: RES, 0, 5%, 0.1 W, 0603; Manufacturer: Yageo; Power_W: 100mW; TempCo: 200 ppm/C; Value_Code: 0000; Value: 0; EIA_Code: E24; SizeX_mm: 1.6; SizeZ_mm: 1; Value2: 0.1W; SizeArea_mm2: 1.28; AEC Qualified: N; VDC_V: 75V; AEC Category: Q200; SizeY_mm: 0.8; SizeAreaWB_mm2: 4.68
R21 R39 = CMP-0025958-3: RES, 10.0 k, 1%, 0.063 W, AEC-Q200 Grade 0, 0402; Manufacturer: Vishay-Dale; Power_W: 63mW; TempCo: 100 ppm/C; Value_Code: 10k0; Value: 10.0k; EIA_Code: E96; Res_ohm: 10k; SizeX_mm: 1; SizeY_mm: 0.5; SizeZ_mm: 0.6; Value2: 0.063W; AEC Qualified: Y; VDC_V: 50V; AEC Category: Q200; AEC Grade: 0
R22 = CMP-0026859-2: RES, 1.0 M, 5%, 0.063 W, AEC-Q200 Grade 0, 0402; Manufacturer: Vishay-Dale; Value: 1.0Meg; Res_ohm: 1M; Value_Code: 1M00; Power_W: 63mW; Value2: 0.063W; VDC_V: 50V; TempCo: 200 ppm/C; SizeArea_mm2: 0.5; SizeX_mm: 1; SizeZ_mm: 0.6; EIA_Code: E24; AEC Category: Q200; AEC Qualified: Y; AEC Grade: 0
R23 = CMP-0017792-3: RES, 0.56, 1%, 0.25 W, AEC-Q200 Grade 0, 1206; Manufacturer: Panasonic; Power_W: 250mW; TempCo: 250 ppm/C; Value_Code: R560; Value: 0.56; EIA_Code: E96; SizeX_mm: 3.2; SizeY_mm: 1.6; SizeZ_mm: 1.35; Value2: 0.25W; SizeArea_mm2: 5.12; AEC Qualified: Y; AEC Category: Q200; AEC Grade: 0; SizeAreaWB_mm2: 10.92
R24 = CMP-0026436-2: RES, 511, 1%, 0.063 W, AEC-Q200 Grade 0, 0402; Manufacturer: Vishay-Dale; Power_W: 63mW; TempCo: 100 ppm/C; Value_Code: 511R; Value: 511; EIA_Code: E96; SizeX_mm: 1; SizeY_mm: 0.5; SizeZ_mm: 0.6; Value2: 0.063W; AEC Qualified: Y; VDC_V: 50V; AEC Category: Q200; AEC Grade: 0
R25 = CMP-0026453-2: RES, 56.2 k, 1%, 0.063 W, AEC-Q200 Grade 0, 0402; Manufacturer: Vishay-Dale; Power_W: 63mW; TempCo: 100 ppm/C; Value_Code: 56k2; Value: 56.2k; EIA_Code: E96; SizeX_mm: 1; SizeY_mm: 0.5; SizeZ_mm: 0.6; Value2: 0.063W; AEC Qualified: Y; VDC_V: 50V; AEC Category: Q200; AEC Grade: 0
R26 = CMP-0026162-2: RES, 20.0 k, 1%, 0.063 W, AEC-Q200 Grade 0, 0402; Manufacturer: Vishay-Dale; Power_W: 63mW; TempCo: 100 ppm/C; Value_Code: 20k0; Value: 20.0k; EIA_Code: E96; Res_ohm: 20k; SizeX_mm: 1; SizeY_mm: 0.5; SizeZ_mm: 0.6; Value2: 0.063W; AEC Qualified: Y; VDC_V: 50V; AEC Category: Q200; AEC Grade: 0
R27 = CMP-0026016-3: RES, 14.3 k, 1%, 0.063 W, AEC-Q200 Grade 0, 0402; Manufacturer: Vishay-Dale; Power_W: 63mW; TempCo: 100 ppm/C; Value_Code: 14k3; Value: 14.3k; EIA_Code: E96; SizeX_mm: 1; SizeY_mm: 0.5; SizeZ_mm: 0.6; Value2: 0.063W; AEC Qualified: Y; VDC_V: 50V; AEC Category: Q200; AEC Grade: 0
R28 = CMP-0027004-2: RES, 0, 5%, 0.063 W, 0402; Manufacturer: Yageo America; Power_W: 63mW; TempCo: 200 ppm/C; Value_Code: 0000; U/M: EA; Value: 0; EIA_Code: E24; SizeX_mm: 1; SizeY_mm: 0.5; SizeZ_mm: 0.6; Value2: 0.063W; VDC_V: 50V; AEC Category: Q200
R29 = CMP-0026063-3: RES, 191 k, 1%, 0.063 W, AEC-Q200 Grade 0, 0402; Manufacturer: Vishay-Dale; Power_W: 63mW; TempCo: 100 ppm/C; Value: 191k; EIA_Code: E96; SizeX_mm: 1; SizeY_mm: 0.5; SizeZ_mm: 0.6; Value2: 0.063W; AEC Qualified: Y; VDC_V: 50V; AEC Category: Q200; AEC Grade: 0
R30 = CMP-0026750-1: RES, 3.30 k, 1%, 0.063 W, AEC-Q200 Grade 0, 0402; Manufacturer: KOA Speer; Power_W: 63mW; TempCo: 100 ppm/C; Value_Code: 3k30; U/M: EA; Value: 3.30k; Res_ohm: 3.3k; SizeX_mm: 1; SizeY_mm: 0.5; SizeZ_mm: 0.6; Value2: 0.063W; AEC Qualified: Y; VDC_V: 50V; AEC Grade: 0; AEC Category: Q200
R31 = CMP-0026327-2: RES, 39.2 k, 1%, 0.063 W, AEC-Q200 Grade 0, 0402; Manufacturer: Vishay-Dale; Power_W: 63mW; TempCo: 100 ppm/C; Value_Code: 39k2; Value: 39.2k; EIA_Code: E96; SizeX_mm: 1; SizeY_mm: 0.5; SizeZ_mm: 0.6; Value2: 0.063W; AEC Qualified: Y; VDC_V: 50V; AEC Category: Q200; AEC Grade: 0
R32 = CMP-0026027-3: RES, 15.0 k, 1%, 0.063 W, AEC-Q200 Grade 0, 0402; Manufacturer: Vishay-Dale; Power_W: 63mW; TempCo: 100 ppm/C; Value_Code: 15k0; Value: 15.0k; EIA_Code: E96; Res_ohm: 15k; SizeX_mm: 1; SizeY_mm: 0.5; SizeZ_mm: 0.6; Value2: 0.063W; AEC Qualified: Y; VDC_V: 50V; AEC Category: Q200; AEC Grade: 0
R33 = CMP-0077547-1: RES, 115 k, 1%, 0.0625 W, 0402; Manufacturer: Samsung Electro-Mechanics; Power_W: 62.5mW; TempCo: 300 ppm/C; U/M: EA; Value: 115k; EIA_Code: E96; SizeX_mm: 1.0; SizeY_mm: 0.5; SizeZ_mm: 0.6; AEC Qualified: N; VDC_V: 50V; AEC Category: Q200
R34 R41 = CMP-0081856-1: RES, 0, 0%, 0.2 W, AEC-Q200 Grade 0, 0402; Manufacturer: Vishay-Dale; SizeAreaWB_mm2: 3; SizeArea_mm2: 0.5; AEC Qualified: Y; AEC Category: Q200; Value: 0; SizeZ_mm: 0.6; Power_W: 200mW; VDC_V: 50V; Value2: 0.2W; SizeX_mm: 1
R35 = CMP-0023235-5: RES, 680, 1%, 0.1 W, 0603; Manufacturer: Yageo; Power_W: 100mW; TempCo: 100 ppm/C; Value_Code: 680R; Value: 680; SizeX_mm: 1.6; SizeY_mm: 0.8; SizeZ_mm: 1; Value2: 0.1W; SizeArea_mm2: 1.28; AEC Qualified: N; VDC_V: 75V; AEC Category: Q200; SizeAreaWB_mm2: 4.68
R36 = CMP-0026455-2: RES, 576 k, 1%, 0.063 W, AEC-Q200 Grade 0, 0402; Manufacturer: Vishay-Dale; Power_W: 63mW; TempCo: 100 ppm/C; Value: 576k; EIA_Code: E96; SizeX_mm: 1; SizeY_mm: 0.5; SizeZ_mm: 0.6; Value2: 0.063W; AEC Qualified: Y; VDC_V: 50V; AEC Category: Q200; AEC Grade: 0
R37 = CMP-0026543-2: RES, 75.0 k, 1%, 0.063 W, AEC-Q200 Grade 0, 0402; Manufacturer: Vishay-Dale; Power_W: 63mW; TempCo: 100 ppm/C; Value_Code: 75k0; Value: 75.0k; EIA_Code: E96; Res_ohm: 75k; SizeX_mm: 1; SizeY_mm: 0.5; SizeZ_mm: 0.6; Value2: 0.063W; AEC Qualified: Y; VDC_V: 50V; AEC Category: Q200; AEC Grade: 0
R38 = CMP-0026859-2: RES, 1.0 M, 5%, 0.063 W, AEC-Q200 Grade 0, 0402; Manufacturer: Vishay-Dale; Power_W: 63mW; TempCo: 200 ppm/C; Value_Code: 1M00; Value: 1.0Meg; EIA_Code: E24; Res_ohm: 1M; SizeX_mm: 1; SizeY_mm: 0.5; SizeZ_mm: 0.6; Value2: 0.063W; AEC Qualified: Y; VDC_V: 50V; AEC Category: Q200; AEC Grade: 0
R40 = CMP-0023253-5: RES, 6.80 k, 1%, 0.1 W, 0603; Manufacturer: Yageo; Power_W: 100mW; TempCo: 100 ppm/C; Value_Code: 6k80; Value: 6.80k; Res_ohm: 6.8k; SizeX_mm: 1.6; SizeY_mm: 0.8; SizeZ_mm: 1; Value2: 0.1W; SizeArea_mm2: 1.28; AEC Qualified: N; VDC_V: 75V; AEC Category: Q200; SizeAreaWB_mm2: 4.68
R42 = CMP-0078244-2: RES, 30.0 k, 1%, 0.063 W, AEC-Q200 Grade 0, 0402; Manufacturer: Vishay-Dale; Power_W: 63mW; Green_Lifecycle: Active; TempCo: 100 ppm/C; Value_Code: 30k0; Green_REACh: Passed; Value: 30.0k; Res_ohm: 30k; SizeX_mm: 1; SizeY_mm: 0.5; SizeZ_mm: 0.6; Value2: 0.063W; AEC Qualified: Y; VDC_V: 50V; AEC Grade: 0; AEC Category: Q200
RT1 = CMP-0002523-3: Thermistor NTC, 47k ohm, 5%, 0603; Manufacturer: MuRata; TaMax_C: 125°C; SizeX_mm: 1.6; SizeY_mm: 0.8; TaMin_C: -40°C; Power_W: 100mW; SizeZ_mm: 1; SizeArea_mm2: 1.28; SizeAreaWB_mm2: 4.68; U/M: EA
T2 = CMP-0087465-1: Lm=200uH, Llk=5uH / P:S1:S2:A = 40:10:10:15; Manufacturer: Renco Electronics; AEC Qualified: No; SizeZ_mm: 0.66inch; DCR_ohm: 0.1; Ind_H: 110µH; Ns1toNp: 2.5:0.5:1:0.5:1
U3 = CMP-0033201-3: 0.5% Accuracy Low-Voltage Adjustable Precision Shunt Regulator, DCK0006A (SOT-SC70-6); Manufacturer: Texas Instruments; VO Adj(Max)(V): 6; Initial Accuracy @ 25/deg C(%): 0.5; Eco-Plan: Green (RoHS & no Sb/Br); Iout/Iz(Max)(mA): 15; Rating: Catalog; Temp Coeff(Max)(ppm/ degree C): 129; VO Adj(Min)(V): 1.24; Min Iz for Regulation(uA): 80; AEC Category: Q200; AEC Qualified: N; CompType: IC; SizeAreaWB_mm2: 9.3; SizeArea_mm2: 4.2; SizeX_mm: 2.1; SizeY_mm: 2.0; SizeZ_mm: 1.1
U4 = CMP-0860377-2: 4-A/6-A, Single-Channel Reinforced Isolation Gate Driver with High Noise Immunity, DWV0008A (SOIC-8); Manufacturer: Texas Instruments; SizeX_mm: 11.5; SizeArea_mm2: 67.275; SizeAreaWB_mm2: 105.975; CompType: IC; SizeZ_mm: 2.8; SizeY_mm: 5.85; AEC Category: Q200; AEC Qualified: N
U5 = CMP-0086087-1: UCC28781RTW, RTW0024B (WQFN-24); Manufacturer: Texas Instruments; SizeY_mm: 4; SizeZ_mm: 0.8; AEC Category: Q200; SizeArea_mm2: 16; CompType: IC; AEC Qualified: N; SizeAreaWB_mm2: 25
U6 = CMP-0087394-2: Optoisolator Transistor Output 5000Vrms 1 Channel 6-SO; Manufacturer: Toshiba; CTR (Max): 300%; CTR (Min): 100%; SizeZ_mm: 2.3mm
U7 = CMP-0066199-1: 2.5V Low Iq Adjustable Precision Shunt Regulator, DBZ0003A (SOT-23-3); Manufacturer: Texas Instruments; SizeArea_mm2: 7.5; SizeAreaWB_mm2: 14.0; SizeX_mm: 2.5; SizeY_mm: 3.0; SizeZ_mm: 1.12; CompType: IC; U/M: EA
